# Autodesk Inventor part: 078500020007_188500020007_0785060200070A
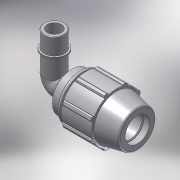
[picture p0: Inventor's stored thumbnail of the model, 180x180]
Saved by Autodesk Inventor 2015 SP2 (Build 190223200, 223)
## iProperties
Created: 2017-02
Part Number: 078500020007_188500020007_0785060200070A
Material: PVC-Piping
Description: PLASSON 90° ELBOW MALE ADAPTOR 20-3/4"
Document SubType Name: Modeling
Designer: KIM
Mass: 92.6774 g
Surface Area: 199.44 cm^2
Volume: 66.1981 cm^3
Density: 1.4 g/cm^3
Appearance: Smooth - White
Author: KIM
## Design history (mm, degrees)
derived "07850.ipt"
feature "Solid1::07850.ipt"
tag "TaggingFeature1"
body "Solid1"
other parameters: "d4" = 6.33333, "d5" = 19, "d7" = 48, "d9" = 10.85714, "d11" = 2.53333, "d13" = 120 deg, "d15" = 12 deg, "d16" = 41.76, "d18" = 1, "d19" = 35 deg, "d20" = 17.5 deg, "d21" = 44.64, "d23" = 0, "d25" = 360 deg, "d27" = 0.96, "d33" = 0.4, "d42" = 28.12, "d43" = 1.44, "d46" = 0.6, "d51" = 76, "d68" = 2.53333, "d72" = 43, "d73" = 26.441, "d74" = 18, "d75" = 30.40715, "d76" = 18.5087, "d77" = 19.8, "d79" = 10.5764, "d80" = 0.79323, "d83" = 0, "d84" = 0, "d91" = 36, "d93" = 57, "d94" = 26.441, "d95" = 18.5087, "d96" = 7.6, "d97" = 50 deg, "E_" = 48, "A_" = 76, "l_" = 57, "l_2" = 18, "A_1" = 43, "R_" = 26.441
